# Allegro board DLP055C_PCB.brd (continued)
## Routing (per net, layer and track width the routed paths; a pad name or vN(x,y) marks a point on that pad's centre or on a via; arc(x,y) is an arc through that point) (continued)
DMD_DMUX: length 9.9
  TOP w0.191: R674.1 158.61,68.64 158.42,68.64 158.4,68.62 158.17,68.62 157.34,67.8 157.34,65.71 156.48,64.86 153.9,64.86 J502.2
DMD_DMUX0: length 32
  LY3 w0.122: J502.1 150.18,67.02 151.04,67.88 160.14,67.88 163.77,71.5 166.12,71.5 166.82,70.8 169.72,70.8 172.39,73.47 v1(177.07,73.47)
  BOTTOM w0.191: R671.2 v1(177.07,73.47)
DMD_HSSI0_CLK_N: length 22.5
  TOP w0.102: U15.AJ25 165.54,97.81 166.53,97.81 166.55,97.83 166.71,97.83 166.91,98.03 166.99,98.03
  TOP w0.127: 166.99,98.03 169.54,98.03 176.6,105.1 176.6,107.29 179.03,109.72 179.93,109.72 180.03,109.63 J7.18
DMD_HSSI0_CLK_P: length 22.5
  TOP w0.102: U15.AK25 165.65,98.4 165.53,98.28 165.53,98.1 165.62,98.01 166.45,98.01 166.47,98.03 166.63,98.03 166.69,98.09 166.69,98.16 166.87,98.34 166.99,98.34
  TOP w0.127: J7.19 180.03,110.13 179.93,110.03 178.91,110.03 176.29,107.42 176.29,105.22 169.41,98.34 166.99,98.34
DMD_HSSI0_N_0: length 25
  TOP w0.102: 166.99,101.76 166.98,101.76 166.91,101.83 166.88,101.83 166.52,101.83 166.5,101.81 165.53,101.81 U15.AJ29
  TOP w0.127: 166.99,101.76 167.27,101.76 172.76,107.25 172.76,110.72 179.76,117.72 179.93,117.72 180.03,117.63 J7.34
DMD_HSSI0_N_1: length 26
  TOP w0.102: 166.99,100.72 166.99,100.72 166.98,100.72 166.81,100.72 166.79,100.73 166.42,100.73 166.33,100.82 166.2,100.82 166.19,100.82 165.71,100.82 165.7,100.82 165.2,100.82 165.19,100.82 164.71,100.82 164.7,100.82 164.2,100.82 164.19,100.82 163.71,100.82 163.7,100.82 163.53,100.82 U15.AG28
  TOP w0.127: J7.30 179.69,115.63 173.74,109.68 173.74,107.12 167.39,100.77 167.17,100.77 167.12,100.72 166.99,100.72
DMD_HSSI0_N_2: length 23.6
  TOP w0.102: U15.AJ27 165.54,99.81 166.46,99.81 166.46,99.81 166.48,99.81 166.5,99.83 166.59,99.83 166.86,99.83 166.86,99.83 166.92,99.83 166.97,99.78 166.97,99.77 166.98,99.75 166.99,99.75
  TOP w0.127: 166.99,99.75 168.29,99.75 174.64,106.11 174.64,108.61 179.76,113.72 179.93,113.72 180.03,113.63 J7.26
DMD_HSSI0_N_3: length 24.9
  TOP w0.102: 166.99,98.74 166.87,98.74 166.83,98.77 166.78,98.77 166.67,98.77 166.67,98.77 166.42,98.77 166.4,98.79 163.56,98.79 U15.AG26
  TOP w0.127: J7.22 180.03,111.63 179.93,111.72 179.53,111.72 175.65,107.85 175.65,105.83 168.79,98.97 167.7,98.97 167.46,98.74 166.99,98.74
DMD_HSSI0_N_4: length 24
  TOP w0.102: 166.99,96.73 166.7,96.73 166.66,96.77 166.47,96.77 166.45,96.78 163.56,96.78 U15.AG24
  TOP w0.127: 166.99,96.73 167.25,96.73 167.59,97.06 170.1,97.06 177.62,104.58 177.62,106.46 178.88,107.72 179.93,107.72 180.03,107.63 J7.14
DMD_HSSI0_N_5: length 20.9
  TOP w0.102: U15.AJ23 165.54,95.81 166.53,95.81 166.56,95.83 166.68,95.83 166.92,96.07 166.99,96.07
  TOP w0.127: J7.10 180.03,105.63 179.93,105.72 179.37,105.72 178.71,105.06 178.71,104.3 170.48,96.07 166.99,96.07
DMD_HSSI0_N_6: length 22.1
  TOP w0.102: 166.99,94.69 166.87,94.69 166.82,94.73 166.46,94.73 166.41,94.78 163.57,94.78 U15.AG22
  TOP w0.127: J7.6 180.03,103.63 179.93,103.72 179.71,103.72 171.34,95.36 167.75,95.36 167.51,95.12 167.51,95.08 167.12,94.69 166.99,94.69
DMD_HSSI0_N_7: length 21.3
  TOP w0.102: U15.AJ21 165.56,93.79 166.99,93.79
  TOP w0.127: 166.99,93.79 167.33,93.79 168.17,94.63 172.44,94.63 175,97.19 177.44,97.19 178.66,98.41 178.66,101.28 179.11,101.72 179.93,101.72 180.03,101.63 J7.2
DMD_HSSI0_P_0: length 24.8
  TOP w0.102: 166.99,102.07 166.87,102.07 166.83,102.03 166.8,102.03 166.44,102.03 166.43,102.02 165.62,102.02 165.53,102.11 165.53,102.28 165.65,102.4 U15.AK29
  TOP w0.127: J7.35 180.03,118.13 179.93,118.03 179.63,118.03 172.45,110.85 172.45,107.38 167.14,102.07 166.99,102.07
DMD_HSSI0_P_1: length 26
  TOP w0.102: U15.AH28 163.65,101.4 163.51,101.26 163.51,101.12 163.61,101.02 163.78,101.02 163.79,101.02 164.11,101.02 164.11,101.02 164.78,101.02 164.79,101.02 165.11,101.02 165.11,101.02 165.78,101.02 165.79,101.02 166.11,101.02 166.11,101.02 166.41,101.02 166.5,100.93 166.89,100.93 166.99,101.03
  TOP w0.127: 166.99,101.03 167.04,101.08 167.27,101.08 173.44,107.25 173.44,109.81 179.56,115.93 179.84,115.93 180.03,116.13 J7.31
DMD_HSSI0_P_2: length 23.5
  TOP w0.102: U15.AK27 165.65,100.4 165.51,100.26 165.51,100.12 165.63,100.01 166.38,100.01 166.38,100.01 166.4,100.01 166.42,100.03 166.67,100.03 166.67,100.03 166.78,100.03 166.84,100.03 166.87,100.06 166.99,100.06
  TOP w0.127: 166.99,100.06 168.16,100.06 174.34,106.24 174.34,108.74 179.63,114.03 179.93,114.03 180.03,114.13 J7.27
DMD_HSSI0_P_3: length 24.8
  TOP w0.102: 166.99,99.04 166.98,99.04 166.97,99.03 166.97,99.02 166.92,98.97 166.86,98.97 166.86,98.97 166.59,98.97 166.5,98.97 166.48,98.99 163.64,98.99 163.51,99.12 163.51,99.26 163.65,99.4 U15.AH26
  TOP w0.127: 166.99,99.04 167.34,99.04 167.57,99.28 168.66,99.28 175.35,105.96 175.35,107.98 179.4,112.03 179.93,112.03 180.03,112.13 J7.23
DMD_HSSI0_P_4: length 23.9
  TOP w0.102: U15.AH24 163.65,97.4 163.53,97.28 163.53,97.11 163.65,96.99 166.53,96.99 166.55,96.97 166.74,96.97 166.77,96.94 166.9,96.94 166.97,97 166.97,97.02 166.98,97.04 166.99,97.04
  TOP w0.127: J7.15 180.03,108.13 179.93,108.03 178.76,108.03 177.31,106.59 177.31,104.71 169.97,97.37 167.46,97.37 167.13,97.04 166.99,97.04
DMD_HSSI0_P_5: length 20.8
  TOP w0.102: 166.99,96.38 166.95,96.38 166.6,96.03 166.47,96.03 166.46,96.01 165.62,96.01 165.53,96.11 165.53,96.28 165.65,96.4 U15.AK23
  TOP w0.127: J7.11 180.03,106.13 179.93,106.03 179.24,106.03 178.41,105.19 178.41,104.43 170.36,96.38 166.99,96.38
DMD_HSSI0_P_6: length 22
  TOP w0.102: U15.AH22 163.65,95.4 163.52,95.27 163.52,95.11 163.65,94.98 166.49,94.98 166.54,94.93 166.93,94.93 166.99,94.99
  TOP w0.127: J7.7 180.03,104.13 179.93,104.03 179.58,104.03 171.22,95.67 167.63,95.67 167.2,95.24 167.2,95.21 166.99,94.99
DMD_HSSI0_P_7: length 21.2
  TOP w0.102: 166.99,94.09 166.98,94.09 166.97,94.08 166.97,94.07 166.89,93.99 165.65,93.99 165.53,94.11 165.53,94.28 165.65,94.4 U15.AK21
  TOP w0.127: J7.3 180.03,102.13 179.93,102.03 178.98,102.03 178.35,101.41 178.35,98.53 177.31,97.49 174.88,97.49 172.31,94.93 168.05,94.93 167.2,94.09 166.99,94.09
DMD_HSSI1_CLK_N: length 32.4
  TOP w0.102: U15.AG7 163.57,79.78 166.36,79.78 166.37,79.76 166.95,79.76 166.98,79.73 166.99,79.73
  TOP w0.127: J10.18 180.03,60.1 179.93,60.19 178.42,60.19 174.57,64.04 174.57,70.58 173.57,71.58 173.57,75.24 169.08,79.73 166.99,79.73
DMD_HSSI1_CLK_P: length 32.3
  TOP w0.102: U15.AH7 163.65,80.4 163.55,80.3 163.55,80.09 163.65,79.98 166.44,79.98 166.46,79.97 166.82,79.97 166.83,79.98 166.92,79.98 166.97,80.04 166.99,80.04
  TOP w0.127: J10.19 180.03,60.6 179.93,60.5 178.54,60.5 174.88,64.17 174.88,70.71 173.88,71.71 173.88,75.36 169.2,80.04 166.99,80.04
DMD_HSSI1_N_0: length 30.8
  TOP w0.102: U15.AG11 163.57,83.78 166.93,83.78 166.98,83.73 166.99,83.73
  TOP w0.127: 166.99,83.73 171.46,83.73 173.61,81.59 174.83,81.59 177.54,78.87 177.54,76.84 177.24,76.54 177.24,74.58 177.72,74.1 177.72,68.82 178.34,68.19 179.93,68.19 180.03,68.1 J10.34
DMD_HSSI1_N_1: length 28.8
  TOP w0.102: U15.AJ10 164.98,83.36 165.01,83.36 165.55,82.83 165.69,82.83 165.71,82.82 166.19,82.82 166.2,82.83 166.45,82.83 166.45,82.83 166.81,82.83 166.81,82.83 166.93,82.83 166.98,82.78 166.99,82.78
  TOP w0.127: J10.30 180.03,66.1 179.93,66.19 178.06,66.19 176.98,67.27 176.98,72.05 176.3,72.73 176.3,77.51 171.03,82.78 166.99,82.78
DMD_HSSI1_N_2: length 31.3
  TOP w0.102: 166.99,81.73 166.98,81.73 166.95,81.76 166.37,81.76 166.35,81.78 163.57,81.78 163.05,82.3 163.05,82.3 U15.AG9
  TOP w0.127: 166.99,81.73 170.6,81.73 175.46,76.87 175.46,72.28 176.2,71.54 176.2,66.45 178.46,64.19 179.93,64.19 180.03,64.1 J10.26
DMD_HSSI1_N_3: length 30.1
  TOP w0.102: 166.99,80.75 166.97,80.75 166.92,80.8 166.84,80.8 166.81,80.83 166.45,80.83 166.43,80.8 165.54,80.8 U15.AJ8
  TOP w0.127: J10.22 180.03,62.1 179.93,62.19 178.12,62.19 175.39,64.92 175.39,71.04 174.61,71.82 174.61,75.98 169.84,80.75 166.99,80.75
DMD_HSSI1_N_4: length 30.8
  TOP w0.102: U15.AJ6 165.05,79.3 165.24,79.3 165.35,79.2 165.35,79.01 165.54,78.81 166.44,78.81 166.45,78.83 166.81,78.83 166.83,78.81 166.92,78.81 166.97,78.76 166.99,78.76
  TOP w0.127: J10.14 180.03,58.1 179.98,58.14 178.59,58.14 173.81,62.93 173.81,69.93 172.47,71.27 172.47,74.1 167.81,78.76 166.99,78.76
DMD_HSSI1_N_5: length 33
  TOP w0.102: U15.AG5 163.57,77.77 163.78,77.77 163.79,77.78 164.11,77.78 164.11,77.77 164.78,77.77 164.79,77.78 165.11,77.78 165.11,77.77 165.78,77.77 165.79,77.78 166.11,77.78 166.11,77.77 166.36,77.77 166.37,77.76 166.75,77.76 166.87,77.7
  TOP w0.127: 166.87,77.7 167,77.63 167.18,77.54 171.32,73.41 171.32,71.06 172.94,69.43 172.94,61.99 178.74,56.19 179.93,56.19 180.03,56.1 J10.10
DMD_HSSI1_N_6: length 32
  TOP w0.102: 166.99,76.56 166.93,76.56 166.71,76.78 165.56,76.78 U15.AJ4
  TOP w0.127: 166.99,76.56 166.99,76.56 168.76,74.8 168.76,72.25 170.2,70.81 170.2,70.37 172.06,68.52 172.06,61.04 175.13,57.97 175.13,57.74 178.68,54.19 179.93,54.19 180.03,54.1 J10.6
DMD_HSSI1_N_7: length 32.7
  TOP w0.102: U15.AJ2 165.56,74.78 166.92,74.78 166.97,74.73 166.99,74.73
  TOP w0.127: J10.2 180.03,52.1 179.93,52.19 179.03,52.19 171.29,59.93 171.29,68.06 168.79,70.55 167.9,70.55 167.44,71.01 167.44,72.4 167.8,72.76 167.8,73.95 167.02,74.73 166.99,74.73
DMD_HSSI1_P_0: length 30.7
  TOP w0.102: U15.AH11 163.65,84.4 163.55,84.3 163.55,84.09 163.65,83.98 166.94,83.98 166.99,84.03
  TOP w0.127: J10.35 180.03,68.6 179.93,68.5 178.47,68.5 178.02,68.94 178.02,74.22 177.54,74.71 177.54,76.41 177.85,76.72 177.85,79 174.95,81.89 173.73,81.89 171.59,84.03 166.99,84.03
DMD_HSSI1_P_1: length 28.7
  TOP w0.102: 166.99,83.08 166.98,83.08 166.93,83.03 166.37,83.03 166.37,83.03 166.12,83.03 166.11,83.02 165.79,83.02 165.77,83.03 165.63,83.03 165.53,83.14 165.53,83.28 165.65,83.4 U15.AK10
  TOP w0.127: 166.99,83.08 171.16,83.08 176.6,77.64 176.6,72.86 177.29,72.18 177.29,67.4 178.18,66.5 179.93,66.5 180.03,66.6 J10.31
DMD_HSSI1_P_2: length 31.1
  TOP w0.102: U15.AH9 163.65,82.4 163.55,82.3 163.55,82.09 163.65,81.99 166.44,81.99 166.45,81.97 166.81,81.97 166.83,81.99 166.92,81.99 166.97,82.04 166.99,82.04
  TOP w0.127: J10.27 180.03,64.6 179.93,64.5 178.58,64.5 176.51,66.58 176.51,71.66 175.76,72.4 175.76,77 170.72,82.04 166.99,82.04
DMD_HSSI1_P_3: length 29.9
  TOP w0.102: 166.99,81.06 166.98,81.06 166.96,81.03 166.37,81.03 166.34,81.01 165.63,81.01 165.55,81.09 165.55,81.3 165.65,81.4 U15.AK8
  TOP w0.127: 166.99,81.06 169.96,81.06 174.92,76.1 174.92,71.95 175.7,71.17 175.7,65.05 178.24,62.5 179.93,62.5 180.03,62.6 J10.23
DMD_HSSI1_P_4: length 30.5
  TOP w0.102: 166.99,79.07 166.98,79.07 166.95,79.03 166.37,79.03 166.35,79.02 165.63,79.02 165.55,79.09 165.55,79.3 165.65,79.4 U15.AK6
  TOP w0.127: 166.99,79.07 167.94,79.07 172.78,74.23 172.78,71.39 174.11,70.06 174.11,63.05 178.72,58.45 179.88,58.45 180.03,58.6 J10.15
DMD_HSSI1_P_5: length 32.8
  TOP w0.102: 166.99,77.97 166.45,77.97 166.45,77.98 166.2,77.98 166.19,77.98 165.71,77.98 165.7,77.98 165.2,77.98 165.19,77.98 164.71,77.98 164.7,77.98 164.2,77.98 164.19,77.98 163.71,77.98 163.7,77.98 163.66,77.98 163.55,78.09 163.55,78.3 163.65,78.4 U15.AH5
  TOP w0.127: J10.11 180.03,56.6 179.93,56.5 178.86,56.5 173.25,62.11 173.25,69.55 171.62,71.18 171.62,73.53 167.36,77.79 167.14,77.9 167.02,77.97 166.99,77.97
DMD_HSSI1_P_6: length 31.7
  TOP w0.102: 166.99,76.93 166.91,76.99 165.65,76.99 165.55,77.09 165.55,77.3 165.65,77.4 U15.AK4
  TOP w0.127: 166.99,76.93 167,76.93 167.06,76.86 167.12,76.86 169.06,74.92 169.06,72.38 170.51,70.93 170.51,70.5 172.36,68.64 172.36,61.17 175.43,58.1 175.43,57.87 178.8,54.5 179.93,54.5 180.03,54.6 J10.7
DMD_HSSI1_P_7: length 32.5
  TOP w0.102: 166.99,75.04 166.97,75.04 166.92,74.99 165.65,74.99 165.55,75.09 165.55,75.3 165.65,75.4 U15.AK2
  TOP w0.127: J10.3 180.03,52.6 179.93,52.5 179.15,52.5 171.6,60.05 171.6,68.18 168.92,70.86 168.02,70.86 167.75,71.14 167.75,72.27 168.1,72.63 168.1,74.08 167.14,75.04 166.99,75.04
DMD_LS0_CLK_N: length 47.5
  TOP w0.127: v1(179.43,121.39) 179.7,121.13 J7.41
  TOP w0.191: U15.AG17 v1(163.45,90.9)
  LY12 w0.076: 164.71,88.78 163.86,89.63 163.86,90.49 v1(163.45,90.9)
  LY12 w0.102: 164.71,88.78 166.92,88.78 166.97,88.73 166.99,88.73
  LY12 w0.114: 166.99,88.73 168.31,88.73 171.19,91.61 171.19,107.89 171.9,108.6 172.41,108.6 180.89,117.08 180.89,120.03 179.84,121.07 179.69,121.09 179.62,121.11 v1(179.43,121.39)
DMD_LS0_CLK_P: length 47.5
  TOP w0.127: J7.40 v1(179.29,120.63)
  TOP w0.191: U15.AH17 v1(164.45,90.9)
  LY12 w0.076: 164.77,88.98 164.75,88.98 164.03,89.7 164.03,90.56 164.03,90.56 164.03,90.6
  LY12 w0.102: 164.77,88.98 166.91,88.98 166.97,89.03 166.99,89.03 ; 164.03,90.6 164.01,90.62 164.01,91.3 164.12,91.4 164.35,91.4 164.49,91.26 164.49,90.94 v1(164.45,90.9)
  LY12 w0.114: 166.99,89.03 168.19,89.03 170.89,91.73 170.89,108.01 171.77,108.9 172.29,108.9 180.59,117.2 180.59,119.9 179.71,120.79 179.54,120.8 v1(179.29,120.63)
DMD_LS0_RDATA: length 53.9
  TOP w0.191: v1(178.74,123.1) 179.56,123.1 180.03,122.63 J7.44 ; U15.AH13 v1(164.45,85.9)
  LY12 w0.076: 163.03,90.36 163.03,91.24 163.2,91.41 ; 165.24,91.89 164.82,92.31 164.2,92.31 163.97,92.09
  LY12 w0.102: 163.97,92.09 163.97,91.66 163.72,91.41 163.2,91.41 ; v1(164.45,85.9) 164.96,86.41 164.96,88.1 164.53,88.53 163.56,88.53 162.93,89.16 162.93,90.25 163.03,90.36 ; 165.24,91.89 166.99,91.89
  LY12 w0.122: v1(178.74,123.1) 178.74,123.1 177.24,123.1 175.38,121.24 175.38,116.09 174.8,115.5 172.64,115.5 172.06,114.92 172.06,113.98 168.58,110.5 168.58,106.76 168.88,106.46 168.88,93 167.77,91.89 166.99,91.89
DMD_LS0_WDATA_N: length 42.6
  TOP w0.127: v1(178.74,119.77) 179.06,119.46 179.87,119.46 180.03,119.63 J7.38
  TOP w0.191: U15.AJ16 v1(165.45,89.9)
  LY12 w0.102: v1(165.45,89.9) 165.85,89.5 166.08,89.27 166.8,89.27 166.85,89.32 166.99,89.32
  LY12 w0.114: v1(178.74,119.77) 179.06,119.46 179.92,119.46 180.24,119.14 180.24,118.21 170.23,108.2 170.23,92.22 168.97,90.97 168.01,90.97 167.4,90.36 167.4,89.66 167.06,89.32 166.99,89.32
DMD_LS0_WDATA_P: length 42.6
  TOP w0.127: v1(178.74,118.9) 179.01,119.16 179.99,119.16 180,119.16 180.03,119.13 J7.37
  TOP w0.191: U15.AK16 v1(166.45,89.9)
  LY12 w0.102: 166.99,89.67 166.84,89.52 166.76,89.52 166.71,89.47 166.16,89.47 166.05,89.58 166.05,89.59 166.01,89.62 166.01,90.38 166.12,90.48 166.35,90.48 166.45,90.38 v1(166.45,89.9)
  LY12 w0.114: v1(178.74,118.9) 179.01,119.16 179.8,119.16 179.94,119.02 179.94,118.33 169.93,108.32 169.93,92.34 168.85,91.26 167.88,91.26 167.1,90.48 167.1,89.78 166.99,89.67
DMD_LS1_CLK_N: length 38
  TOP w0.191: U15.AG15 v1(163.45,87.9) ; J10.41 179.84,71.6 179.84,71.6 179.42,71.6 179.42,71.6 178.74,71.6 178.6,71.46 v1(178.56,71.46)
  BOTTOM w0.178: 166.99,81.12 166.29,81.82 164.36,81.82 163.93,82.25 163.93,83.22 162.96,84.18 162.96,87.41 v1(163.45,87.9)
  BOTTOM w0.191: v1(178.56,71.46) 179.02,71.46 179.27,71.21 180.02,71.21 180.41,70.81 180.41,68.77 179.96,68.31 176.56,68.31 167.98,76.89 167.98,80.13 166.99,81.12
DMD_LS1_CLK_P: length 30.4
  TOP w0.191: J10.40 179.84,71.1 179.84,71.1 179.42,71.1 179.42,71.1 179.08,71.1 v1(178.7,70.71) ; U15.AH15 v1(164.45,87.9)
  BOTTOM w0.178: 166.99,83.45 164.82,83.45 163.95,84.31 163.95,87.41 v1(164.45,87.9)
  BOTTOM w0.191: 166.99,83.45 167.31,83.45 168.64,82.12 168.64,76.93 174.86,70.71 v1(178.7,70.71)
DMD_LS1_RDATA: length 23.8
  TOP w0.191: v1(178.61,73.36) 178.88,73.1 J10.44 ; U15.AG13 v1(163.45,85.9)
  LY5 w0.122: v1(178.61,73.36) 169.97,82 169.97,82.48 167.05,85.4 163.94,85.4 v1(163.45,85.9)
DMD_LS1_WDATA_N: length 29.6
  TOP w0.191: v1(178.61,69.94) 178.77,70.1 179.42,70.1 179.42,70.1 179.84,70.1 179.84,70.1 J10.38 ; U15.AJ14 165.47,86.88 166.37,86.88 168.55,84.69 172,84.69 173.58,83.12 175.21,83.12 v1(178.1,80.22)
  LY12 w0.122: v1(178.1,80.22) 178.07,80.19 178.07,77.22 177.44,76.59 177.44,74.4 178.07,73.77 178.07,70.47 v1(178.61,69.94)
DMD_LS1_WDATA_P: length 30.7
  TOP w0.191: U15.AK14 166.76,87.4 167.36,86.8 168.12,86.8 169.62,85.3 172.92,85.3 173.27,84.95 173.27,84.16 173.94,83.5 175.74,83.5 v1(177.97,81.26) ; v1(178.65,69.13) 179.11,69.6 J10.37
  LY12 w0.122: v1(178.65,69.13) 177.75,70.04 177.75,73.54 177.14,74.15 177.14,77.2 177.59,77.66 177.59,80.86 177.97,81.24 v1(177.97,81.26)
DMD_OK: length 1.9
  TOP w0.191: U3.1 v1(76.07,137.16)
  BOTTOM w0.191: R87.2 75.36,137.16 v1(76.07,137.16)
DMD_P1P8V_EN: length 90.3
  TOP w0.191: R867.1 148.27,111.56 151.05,114.34 151.05,119.67 153.41,122.03 155.31,122.03 157.4,119.95 157.4,115.33 160.02,112.71 163.66,112.71 164.5,111.87 164.5,111.85 169.06,107.29 v1(171.66,107.29) ; J10.49 179.9,75.6 179.89,75.6 179.48,75.6 179.45,75.62 179.41,75.62 178.9,76.14 178.9,81.59 181.47,84.15 183.96,84.15 186.25,86.45 186.25,92.81 185.66,93.41 182.8,93.41 182.43,93.03 180.83,93.03 180.05,93.8 178.22,93.8 178,93.59 176.04,93.59 175.26,94.36 175.26,94.74 TP284.1
  LY12 w0.122: v1(171.66,107.29) 174.62,104.33 TP284.1
DMD_PWR_EN: length 95.4
  TOP w0.191: U15.R4 v1(151.45,76.9) ; J7.45 180.03,123.13 179.51,123.65 v1(179.4,123.65) ; v1(178.84,74.1) 179.32,73.62 179.43,73.62 179.46,73.59 179.88,73.59 179.91,73.62 180.97,73.62 J10.45
  LY3 w0.076: 158.89,76.19 158.77,76.31 158.28,76.31 158.27,76.31 158.24,76.31 157.91,75.98
  LY3 w0.102: 158.89,76.19 158.89,75.71 159.16,75.45 166.99,75.45 ; 155.99,73.34 157.91,75.26 157.91,75.98 ; 155.01,73.34 v1(151.45,76.9)
  LY3 w0.122: 155.01,73.34 155.08,73.27 155.92,73.27 155.99,73.34 ; 166.99,75.45 168.53,75.45 168.81,75.17 176.4,75.17 177.52,76.29 178.69,76.29 179.37,75.6 179.37,74.63 v1(178.84,74.1)
  BOTTOM w0.191: v1(178.84,74.1) 179.73,74.1 181.28,75.65 181.28,77.2 183.89,79.82 183.89,84.31 185.47,85.89 185.47,118.98 180.77,123.68 179.44,123.68 v1(179.4,123.65)
DRAIN_SEQ: length 40.3
  TOP w0.191: v1(87.29,95.89) 87.6,96.19 U525.6 ; R887.2 80.94,91.77 U526.2 84.08,91.77 84.58,92.26 84.58,92.97 84.96,93.35 88.24,93.35 88.97,94.09 88.97,94.67 88.36,95.28 87.17,95.28 86.61,95.84 86.61,97.16 v1(87.24,97.79)
  LY12 w0.122: v1(87.24,97.79) 87.78,97.25 87.78,96.38 v1(87.29,95.89) 85.67,97.5 85.67,98.84 83.79,100.72 83.79,104.02 83.18,104.63 v1(83.18,107.78)
  BOTTOM w0.191: R193.1 v1(87.24,97.79) ; U58.2 81.6,107.6 81.78,107.78 v1(83.18,107.78) 84.2,107.78 84.76,108.34 84.76,108.84 U529.4
DRV_MODE: length 2.3
  TOP w0.191: U35.14 144.21,42.52 v1(144.06,42.37)
  BOTTOM w0.191: R145.1 144.87,42.52 144.21,42.52 v1(144.06,42.37)
DRV_TRQ: length 2.5
  TOP w0.191: U35.11 144.41,44.47 144.11,44.78 v1(143.99,44.78)
  BOTTOM w0.191: v1(143.99,44.78) 144.06,44.78 144.36,45.09 R138.1
DYN_BLK: length 5.3
  TOP w0.191: J86.2 136.79,57.84 v1(138.75,57.84) 139.89,57.84 U47.2
  BOTTOM w0.191: R859.1 139.55,57.67 139.39,57.84 v1(138.75,57.84)
DYN_BLK_1: length 3.4
  TOP w0.191: R259.2 145.52,56.85 145.5,56.84 U47.4
DYN_BLK_2: length 3.5
  TOP w0.191: J114.2 147,54.36 146.99,54.37 146.99,56.35 147.02,56.39 R259.1
EEPROM_WP: length 5.3
  TOP w0.191: J72.2 32.7,77.47 U560.7
EXT_ARSTZ: length 6.5
  TOP w0.191: U15.AF29 v1(162.45,102.9)
  BOTTOM w0.191: TP21.1 162.73,107.46 162.93,107.26 162.93,103.38 162.45,102.9 v1(162.45,102.9)
EXT_I2C_EN: length 7.1
  TOP w0.191: J52.2 13.37,104.49 R586.2 17.08,104.48 U559.6
EXT_I2CPWR: length 5.8
  TOP w0.191: F1.1 7.26,102.44 J51.4
  BOTTOM w0.191: J51.4 7.02,102.76 C511.1
EXT_SCL: length 10.6
  TOP w0.191: R863.2 12.82,96.6 v1(12.82,95.97) 12.82,94.7 12.59,94.47 U17.6
  LY3 w0.122: v1(12.82,95.97) 11.86,95.97 11.4,96.43 8.3,96.43 J51.2
EXT_SCL_T: length 12
  TOP w0.191: R861.1 11,96.93 R863.1 v1(11.23,98.07) ; v1(15.74,103.77) 16.08,103.43 U559.8
  BOTTOM w0.191: v1(15.74,103.77) 15.16,103.77 14.5,103.11 14.5,100.31 13.38,99.2 12.35,99.2 v1(11.23,98.07)
EXT_SDA: length 5.8
  TOP w0.191: R864.2 10.59,93.47 U17.3 8.76,93.48 J51.1
EXT_SDA_T: length 16.8
  TOP w0.191: U559.1 16.08,98.64 15.69,98.26 v1(13.25,98.26) 12.37,99.15 10.05,99.15 9.84,98.93 R862.1 ; R864.1 v1(13.14,92.08)
  LY12 w0.122: v1(13.14,92.08) 13.14,94 12.25,94.89 12.25,97.25 v1(13.25,98.26)
FE_3D_LR: length 245.3
  TOP w0.191: v1(119.66,141.48) 119.66,141.98 119.66,141.98 119.66,142.4 119.66,142.4 119.66,142.57 119.66,142.57 119.66,142.99 119.66,142.99 J3.21 ; J42.11 135.37,9.43 135.38,9.43 135.38,9.85 135.37,9.85 v1(135.37,10.4) ; v1(118.22,9.4) 117.69,8.86 114.77,8.86 113.51,7.61 J44.51
  LY3 w0.076: 136.97,74.06 137.22,74.31 145.06,74.31 145.31,74.06 145.64,74.06
  LY3 w0.102: 150.32,73.34 150.77,73.79 v1(151.56,73.79) ; 145.64,74.06 146.25,73.45 147.7,73.45 147.81,73.34 ; 136.97,74.06 136.97,73.74 136.7,73.47 135.88,73.47
  LY3 w0.122: 135.88,73.47 135.4,73.47 135.25,73.62 126.72,73.62 126.21,74.13 123.69,74.13 122.81,75.02 v1(121.69,75.02) ; 147.81,73.34 148.17,72.98 149.97,72.98 150.32,73.34 ; v1(135.37,10.4) 135.37,11.19 134.51,12.05 125.14,12.05 124.79,12.4 121.23,12.4 v1(118.22,9.4)
  LY12 w0.122: v1(121.69,75.02) 123.06,76.39 123.06,81.25 121.11,83.2 121.11,85.98 119.55,87.54 119.55,89.39 121.11,90.94 121.11,93.76 119.45,95.42 119.45,139.49 119.66,139.7 v1(119.66,141.48) ; v1(151.56,73.79) 151.56,73.27 150.72,72.42 150.72,68.67 151.33,68.06 153.16,68.06 153.92,67.29 153.92,65.31 153.44,64.83 152.72,64.83 151.45,63.55 151.45,62.06 150.03,60.64 148.21,60.64 148.04,60.64 146.13,58.72 146.13,58.58 146.1,58.56 146.1,58.52 146.1,58.52 146.1,57.74 145.94,57.59 145.94,57.12 145.94,56.24 145,55.3 143.99,55.3 143.53,54.85 143.53,52.48 143.03,51.98 143.03,51.86 143.01,51.84 143.01,49.76 143.03,49.74 143.03,49.63 144.47,48.2 147.73,48.2 149.03,46.9 152.11,46.9 154.45,44.56 154.45,34.73 153.16,33.44 153.16,31.48 154.71,29.93 154.71,16.7 152.9,14.89 152.9,13.55 151.23,11.87 136.84,11.87 v1(135.37,10.4) ; v1(118.22,9.4) 118.22,11.85 117.22,12.86 117.22,16.21 115.02,18.41 J61.1
  BOTTOM w0.191: R260.1 151.57,74.58 151.56,74.57 v1(151.56,73.79)
FE_PROJ_ON: length 47.5
  TOP w0.191: v1(57.76,142.76) R88.1 59.06,143.08 U565.1
  LY3 w0.122: v1(57.76,142.76) 58.35,142.17 61.36,142.17 61.97,141.56 75.89,141.56 76.27,141.94 87.47,141.94 90.9,138.52 97.56,138.52 J68.1
FE_SPR1: length 3.3
  TOP w0.191: TP7.1 123.82,141.71 123.66,141.87 123.66,142.56 123.65,142.57 123.65,142.99 123.66,142.99 J3.13
FIELD: length 138.4
  TOP w0.191: J44.4 v1(89.65,8.86)
  TOP w0.381: U15.C15 v1(138.45,87.9)
  LY3 w0.076: 135.94,87.79 136.24,87.49 138.05,87.49 138.45,87.89
  LY3 w0.102: 135.94,87.79 135.88,87.79 ; v1(138.45,87.9) 138.45,87.89
  LY3 w0.122: v1(93.04,87.81) 93.04,88.78 93.16,88.9 93.16,89.04 94.81,90.69 105.46,90.69 105.83,90.33 110.24,90.33 110.62,90.72 110.63,90.72 111.74,91.83 119.02,91.83 122.17,88.68 124.61,88.68 125.22,88.07 128.22,88.07 128.22,88.08 128.23,88.08 128.25,88.1 128.64,88.1 128.67,88.08 128.84,88.08 129.13,87.79 135.88,87.79
  LY12 w0.122: v1(93.04,87.81) 92.12,86.89 92.12,63.12 98.34,56.89 98.34,51.47 89.46,42.59 89.46,19.73 89.1,19.38 89.1,12.9 90.14,11.86 90.14,9.81 89.65,9.32 v1(89.65,8.86)
FP_A_A_N: length 108.5
  TOP w0.127: J42.47 153.38,8.64 153.28,8.74 153.28,10.54 154.66,11.92 154.66,12.73 TP132.1 154.87,13.34 154.46,13.75 154.46,14.28 v1(154.74,14.57)
  TOP w0.381: U15.G2 v1(142.45,74.9)
  LY10 w0.076: v1(142.45,74.9) 142.86,74.49 144.86,74.49
  LY10 w0.102: 145.91,73.55 145.91,73.6 145.03,74.49 144.86,74.49
  LY10 w0.114: 145.91,73.55 146.1,73.37 149.16,73.37 149.24,73.28 152.85,73.28 153.64,72.49 153.64,70.69 154.22,70.12 154.22,65.25 156.23,63.24 156.23,61.64 155.68,61.09 155.68,59.73 156.99,58.42 158.38,58.42 158.86,57.93 158.86,55.52 158.41,55.06 155.79,55.06 155.1,54.37 155.1,54.04 155.69,53.45 157.54,53.45 158.07,52.93 158.07,51.84 156.13,49.9 156.13,49.26 156.58,48.81 157.46,48.81 158.24,48.03 158.24,44.31 160.95,41.6 160.95,26.25 157.75,23.05 157.75,22.26 160.04,19.97 160.04,17.21 159.63,16.8 158.54,16.8 158.21,17.13 158.21,19.2 157.94,19.47 157.54,19.47 157.27,19.2 157.27,17.14 156.85,16.72 156.06,16.72 155.65,17.14 155.65,19.07 155.36,19.36 154.75,19.36 154.46,19.07 154.46,14.86 v1(154.74,14.57)
FP_A_A_P: length 108.4
  TOP w0.127: J42.46 152.87,8.64 152.97,8.74 152.97,10.67 154.35,12.05 154.35,12.34 TP135.1 154.03,13.34 154.15,13.46 154.15,14.28 v1(153.87,14.57)
  TOP w0.381: U15.G1 v1(142.45,73.9)
  LY10 w0.076: 144.86,74.29 144.85,74.29 144.84,74.3 144.79,74.3 144.77,74.31 142.86,74.31 v1(142.45,73.9)
  LY10 w0.102: 145.7,73.34 145.69,73.35 145.69,73.46 144.86,74.29
  LY10 w0.114: v1(153.87,14.57) 154.16,14.87 154.16,19.2 154.63,19.66 155.48,19.66 155.95,19.2 155.95,17.26 156.19,17.02 156.73,17.02 156.97,17.26 156.97,19.32 157.41,19.76 158.07,19.76 158.51,19.32 158.51,17.25 158.67,17.1 159.5,17.1 159.74,17.34 159.74,19.85 157.45,22.14 157.45,23.17 160.66,26.38 160.66,41.47 157.94,44.19 157.94,47.91 157.34,48.51 156.46,48.51 155.83,49.14 155.83,50.02 157.77,51.96 157.77,52.8 157.42,53.15 155.56,53.15 154.8,53.92 154.8,54.49 155.67,55.36 158.28,55.36 158.56,55.64 158.56,57.81 158.25,58.12 156.87,58.12 155.38,59.61 155.38,61.21 155.93,61.76 155.93,63.12 153.92,65.13 153.92,69.99 153.34,70.57 153.34,72.36 152.72,72.98 149.12,72.98 149.03,73.07 145.97,73.07 145.7,73.34
FP_A_B_N: length 108.6
  TOP w0.127: J42.44 151.87,8.64 151.78,8.74 151.78,10.85 152.55,11.62 152.55,14.44 TP138.1 152.68,15.24 152.55,15.37 152.55,15.93 v1(152.84,16.22)
  TOP w0.381: U15.F4 v1(141.45,76.9)
  LY10 w0.076: 142.1,73.34 142.1,73.36 142.03,73.42 142.03,76.16 141.7,76.49 141.52,76.49 141.45,76.56 v1(141.45,76.9)
  LY10 w0.114: 142.1,73.34 142.1,73.12 142.24,72.98 143.24,72.98 144.55,71.67 146.59,71.67 147.16,71.1 147.16,60.49 147.68,59.97 149.24,59.97 149.76,60.49 149.76,63.61 150.78,64.63 153.19,64.63 154.5,63.31 154.5,59.34 155.29,58.54 155.29,56.24 153.84,54.78 153.84,52.53 154.53,51.84 154.53,48.83 157.08,46.28 157.08,43.62 159.76,40.93 159.76,28.52 158.88,27.63 150.3,27.63 149.76,27.09 149.76,24.58 150.3,24.04 154.29,24.04 155.16,23.16 155.16,21.4 152.73,18.96 152.73,16.69 152.84,16.58 v1(152.84,16.22)
FP_A_B_P: length 108.5
  TOP w0.127: J42.43 151.38,8.64 151.47,8.74 151.47,10.97 152.25,11.75 152.25,14.44 TP141.1 152.12,15.24 152.25,15.37 152.25,15.93 v1(151.96,16.22)
  TOP w0.381: U15.F3 v1(141.45,75.9)
  LY10 w0.076: 141.8,73.34 141.8,73.36 141.86,73.42 141.86,76.09 141.63,76.31 141.52,76.31 141.45,76.24 v1(141.45,75.9)
  LY10 w0.114: 141.8,73.34 141.8,72.99 142.11,72.68 143.12,72.68 144.43,71.37 146.46,71.37 146.86,70.98 146.86,60.37 147.55,59.67 149.36,59.67 150.06,60.37 150.06,63.48 150.9,64.33 153.06,64.33 154.2,63.19 154.2,59.21 155,58.42 155,56.36 153.54,54.9 153.54,52.41 154.23,51.71 154.23,48.7 156.78,46.16 156.78,43.5 159.47,40.81 159.47,28.64 158.75,27.93 150.18,27.93 149.47,27.22 149.47,24.46 150.18,23.75 154.16,23.75 154.87,23.04 154.87,21.52 152.43,19.09 152.43,16.69 v1(151.96,16.22)
FP_A_C_N: length 108.5
  TOP w0.127: v1(150.93,14.44) 150.65,14.16 150.65,13.78 150.65,13.46 150.77,13.34 TP131.1 150.65,12.53 150.65,11.19 150.28,10.82 150.28,8.74 150.38,8.64 J42.41
  TOP w0.381: U15.E2 v1(140.45,74.9)
  LY10 w0.076: v1(140.45,74.9) 140.45,74.56 140.52,74.49 140.7,74.49 141.03,74.16 141.03,73.42 141.1,73.36 141.1,73.34
  LY10 w0.114: 141.1,73.34 141.1,73.13 141.45,72.78 141.45,71.81 143.33,69.93 143.33,62.8 146.35,59.78 146.35,58.71 152.04,53.02 152.04,46.95 155.8,43.19 155.8,29.9 154.56,28.67 148.08,28.67 147.61,29.13 147.61,30.05 148.02,30.45 148.92,30.45 149.51,29.86 152.05,29.86 152.22,30.03 152.22,32.38 151.67,32.94 147.27,32.94 146.74,32.4 146.74,24.41 144.16,21.83 144.16,21.07 144.57,20.66 149.85,20.66 150.82,19.7 150.82,15 150.93,14.88 v1(150.93,14.44)
FP_A_C_P: length 108.3
  TOP w0.127: J42.40 149.87,8.64 149.97,8.74 149.97,10.95 150.34,11.32 150.34,12.53 TP134.1 150.22,13.34 150.34,13.46 150.34,13.65 150.34,14.16 v1(150.06,14.44)
  TOP w0.381: U15.E1 v1(140.45,73.9)
  LY10 w0.076: 140.8,73.34 140.8,73.36 140.86,73.42 140.86,74.08 140.63,74.31 140.52,74.31 140.45,74.24 v1(140.45,73.9)
  LY10 w0.114: 140.8,73.34 140.8,73.01 141.15,72.66 141.15,71.68 143.03,69.81 143.03,62.67 146.05,59.65 146.05,58.58 151.74,52.89 151.74,46.82 155.5,43.07 155.5,30.03 154.44,28.96 148.2,28.96 147.91,29.26 147.91,29.92 148.14,30.15 148.8,30.15 149.39,29.56 152.17,29.56 152.52,29.91 152.52,32.51 151.79,33.24 147.15,33.24 146.44,32.53 146.44,24.53 143.86,21.96 143.86,20.95 144.45,20.36 149.72,20.36 150.52,19.57 150.52,14.91 v1(150.06,14.44)
FP_A_CLK_N: length 108.5
  TOP w0.127: v1(145.22,16.35) 144.93,16.06 144.93,15.68 144.93,15.37 145.06,15.24 TP136.1 144.88,14.39 144.88,11.95 145.78,11.05 145.78,8.74 145.87,8.64 J42.32
  TOP w0.381: U15.H4 v1(143.45,76.9)
  LY10 w0.076: 152.33,76.06 151.4,76.06 150.97,76.49 143.86,76.49 v1(143.45,76.9)
  LY10 w0.102: 154.97,73.55 152.47,76.05 152.33,76.06
  LY10 w0.114: 154.97,73.55 155.09,73.43 155.09,72.66 157.42,70.33 157.42,61.44 159.81,59.05 159.81,53.55 159.26,52.99 159.26,45.08 161.97,42.36 161.97,25.67 160.02,23.72 160.02,22.28 161.03,21.27 161.03,15.17 159.03,13.17 145.99,13.17 145.13,14.03 145.13,15.47 145.94,16.29 145.94,16.75 145.69,17 145.36,17 145.23,16.87 145.23,16.63 145.22,16.63 v1(145.22,16.35)
FP_A_CLK_P: length 108.4
  TOP w0.127: J42.31 145.37,8.64 145.47,8.74 145.47,10.92 144.57,11.82 144.57,14.49 TP139.1 144.5,15.24 144.63,15.37 144.63,15.55 144.63,16.06 v1(144.34,16.35)
  TOP w0.381: U15.H3 v1(143.45,75.9)
  LY10 w0.076: 152.47,75.63 152.22,75.88 151.33,75.88 150.9,76.31 143.86,76.31 v1(143.45,75.9)
  LY10 w0.102: 152.47,75.63 154.76,73.34
  LY10 w0.114: 154.76,73.34 154.79,73.31 154.79,72.54 157.12,70.21 157.12,61.32 159.51,58.92 159.51,53.67 158.96,53.11 158.96,44.95 161.67,42.24 161.67,25.8 159.72,23.84 159.72,22.15 160.73,21.14 160.73,15.29 158.9,13.46 146.11,13.46 145.42,14.15 145.42,15.35 146.24,16.17 146.24,16.88 145.82,17.3 145.24,17.3 144.93,16.99 144.93,16.76 144.81,16.64 144.63,16.64 v1(144.34,16.35)
FP_A_D_N: length 108.4
  TOP w0.127: J42.38 148.87,8.64 148.78,8.74 148.78,14.47 TP137.1 148.93,15.24 148.8,15.37 148.8,15.99 v1(149.03,16.22)
  TOP w0.381: U15.D4 v1(139.45,76.9)
  LY10 w0.076: v1(139.45,76.9) 139.45,76.56 139.52,76.49 139.7,76.49 140.03,76.16 140.03,73.42 140.1,73.36 140.1,73.34
  LY10 w0.114: v1(149.03,16.22) 148.74,16.5 148.74,18.85 147.91,19.69 143.28,19.69 142.76,20.21 142.76,22.03 145.79,25.06 145.79,33.19 146.4,33.8 153.72,33.8 154.61,34.68 154.61,41.46 154.23,41.84 153.22,41.84 152.76,41.38 152.76,35.9 152.53,35.67 151.86,35.67 151.68,35.85 151.68,44.39 151.3,44.77 151.3,45.57 149.55,47.33 149.55,49.08 150.31,49.85 150.31,51.54 147.61,54.23 147.61,55.86 145.31,58.17 143.36,58.17 142.2,59.32 142.2,63.56 141.68,64.08 141.68,67.3 140.67,68.31 139.54,68.31 139.38,68.47 139.38,71.37 140.1,72.08 140.1,73.34
FP_A_D_P: length 108.2
  TOP w0.127: J42.37 148.38,8.64 148.47,8.74 148.47,14.4 TP140.1 148.31,15.24 148.5,15.43 148.5,15.87 v1(148.15,16.22)
  TOP w0.381: U15.D3 v1(139.45,75.9)
  LY10 w0.076: 139.8,73.34 139.8,73.36 139.86,73.42 139.86,76.08 139.63,76.31 139.52,76.31 139.45,76.24 v1(139.45,75.9)
  LY10 w0.114: 139.8,73.34 139.8,72.2 139.08,71.49 139.08,68.35 139.42,68.01 140.55,68.01 141.38,67.18 141.38,63.96 141.91,63.43 141.91,59.2 143.24,57.87 145.18,57.87 147.32,55.74 147.32,54.11 150.01,51.42 150.01,49.97 149.25,49.21 149.25,47.2 151,45.45 151,44.65 151.38,44.27 151.38,35.73 151.74,35.37 152.65,35.37 153.06,35.78 153.06,41.26 153.34,41.54 154.1,41.54 154.31,41.34 154.31,34.8 153.6,34.1 146.27,34.1 145.5,33.32 145.5,25.19 142.46,22.16 142.46,20.08 143.16,19.39 147.79,19.39 148.44,18.73 148.44,16.51 v1(148.15,16.22)
FP_A_E_N: length 108.2
  TOP w0.127: J42.35 147.37,8.64 147.28,8.74 147.28,12.22 146.98,12.51 146.98,12.68 TP130.1 147.09,13.34 146.86,13.57 146.86,14.18 v1(147.12,14.44)
  TOP w0.381: U15.C2 v1(138.45,74.9)
  LY10 w0.076: 138.97,73.34 139.03,73.41 139.03,74.16 138.7,74.49 138.52,74.49 138.45,74.56 v1(138.45,74.9)
  LY10 w0.114: 138.97,73.34 138.93,73.3 138.93,73.21 138.7,72.99 138.7,70.72 137.73,69.75 137.73,68.5 140.33,65.9 140.33,64.32 139.77,63.76 135.11,63.76 134.81,63.46 134.81,60.15 135.1,59.87 137.49,59.87 137.87,60.25 137.87,62.14 138.47,62.74 140.54,62.74 141.17,62.11 141.17,58.25 143.79,55.63 143.79,54.44 144.88,53.35 144.88,49.73 150.75,43.87 150.75,40.22 150.29,39.76 148.14,39.76 147.65,39.26 147.65,37.65 147.16,37.17 141.98,37.17 141.63,36.81 141.63,34.52 142.02,34.12 144.14,34.12 144.7,33.56 144.7,25.6 141.55,22.44 141.55,19.43 142.53,18.46 146.67,18.46 147.4,17.73 147.4,15.83 146.83,15.25 146.83,14.74 v1(147.12,14.44)
FP_A_E_P: length 108.2
  TOP w0.127: v1(146.25,14.44) 146.55,14.14 146.55,13.48 146.41,13.34 TP133.1 146.97,12.09 146.97,8.74 146.87,8.64 J42.34
  TOP w0.381: U15.C1 v1(138.45,73.9)
  LY10 w0.076: 138.7,73.41 138.71,73.42 138.73,73.42 138.74,73.44 138.74,73.49 138.86,73.6 138.86,74.08 138.63,74.31 138.52,74.31 138.45,74.24 v1(138.45,73.9)
  LY10 w0.114: v1(146.25,14.44) 146.53,14.73 146.53,15.38 147.1,15.95 147.1,17.6 146.55,18.16 142.4,18.16 141.25,19.31 141.25,22.57 144.4,25.72 144.4,33.44 144.02,33.82 141.9,33.82 141.33,34.39 141.33,36.94 141.86,37.47 147.04,37.47 147.35,37.78 147.35,39.39 148.02,40.06 150.16,40.06 150.45,40.34 150.45,43.74 144.58,49.61 144.58,53.23 143.49,54.32 143.49,55.51 140.87,58.13 140.87,61.99 140.42,62.44 138.6,62.44 138.17,62.02 138.17,60.13 137.62,59.57 134.97,59.57 134.51,60.03 134.51,63.59 134.99,64.06 139.65,64.06 140.03,64.45 140.03,65.78 137.44,68.38 137.44,69.87 138.4,70.84 138.4,73.11 138.7,73.41
FP_B_A_N: length 108.3
  TOP w0.127: v1(141.41,16.22) 141.12,15.93 141.12,15.55 141.12,15.37 141.25,15.24 TP86.1 141.12,14.44 141.12,11.71 142.78,10.06 142.78,8.74 142.88,8.64 J42.26
  TOP w0.305: U15.D5 v1(139.45,77.9)
  LY10 w0.076: 136.05,77.13 136.24,77.31 138.7,77.31 139.03,77.64 139.03,77.82 139.11,77.9 v1(139.45,77.9)
  LY10 w0.114: v1(141.41,16.22) 141.12,16.51 141.12,16.95 139.33,18.74 139.33,23.09 142.26,26.03 142.26,27.85 137.56,32.55 137.56,35.64 141.88,39.96 141.88,41.18 143.13,42.43 143.13,43.92 141.34,45.7 141.34,47.41 142.69,48.76 142.69,52.03 140.26,54.46 135.16,54.46 133.1,56.52 133.1,58.34 132.28,59.17 128.06,59.17 127.22,60.01 127.22,65.92 128.34,67.04 131.01,67.04 131.71,67.74 131.71,70.51 130.69,71.53 129.12,71.53 128.67,71.99 128.67,73.56 130.08,74.98 131.31,74.98 132.06,74.23 135.37,74.23 135.93,74.79 135.93,77 136.05,77.13
FP_B_A_P: length 108.4
  TOP w0.127: v1(140.53,16.22) 140.82,15.93 140.82,15.42 140.82,15.37 140.69,15.24 TP89.1 140.82,14.44 140.82,11.59 142.47,9.93 142.47,8.74 142.38,8.64 J42.25
  TOP w0.381: U15.C5 v1(138.45,77.9)
  LY10 w0.076: 135.88,77.35 136.01,77.49 138.63,77.49 138.86,77.72 138.86,77.82 138.79,77.9 v1(138.45,77.9)
  LY10 w0.114: 135.88,77.35 135.86,77.35 135.63,77.13 135.63,74.91 135.25,74.53 132.18,74.53 131.43,75.28 129.96,75.28 128.37,73.69 128.37,71.87 129,71.23 130.57,71.23 131.41,70.39 131.41,67.87 130.89,67.34 128.22,67.34 126.92,66.04 126.92,59.88 127.94,58.87 132.15,58.87 132.8,58.22 132.8,56.39 135.04,54.16 140.14,54.16 142.39,51.9 142.39,48.88 141.04,47.53 141.04,45.58 142.83,43.79 142.83,42.55 141.58,41.31 141.58,40.09 137.26,35.76 137.26,32.43 141.96,27.72 141.96,26.15 139.03,23.22 139.03,18.62 140.82,16.83 140.82,16.5 v1(140.53,16.22)
FP_B_B_N: length 108.3
  TOP w0.127: v1(139.5,14.67) 139.22,14.39 139.22,13.46 139.34,13.34 TP79.1 139.22,12.53 139.22,11.92 141.28,9.86 141.28,8.74 141.37,8.64 J42.23
  TOP w0.381: U15.B6 v1(137.45,78.9)
  LY10 w0.076: v1(137.45,78.9) 137.11,78.9 137.03,78.82 137.03,78.64 136.7,78.31 135.96,78.31 135.9,78.25 135.88,78.25
  LY10 w0.114: 135.88,78.25 135.71,78.25 135.5,78.04 135.5,77.53 133.79,75.81 131.27,75.81 130.72,76.37 130.72,77.59 130.39,77.91 129.02,77.91 128.71,77.6 128.71,74.93 127.46,73.68 127.46,67.86 125.41,65.81 125.41,58.89 125.95,58.35 130.62,58.35 131.32,57.65 131.32,54.79 132.53,53.58 139.54,53.58 141.55,51.57 141.55,49.1 140.15,47.7 140.15,43.37 139.5,42.71 136.04,42.71 135.61,42.28 135.61,32.91 141.09,27.42 141.09,26.25 138.22,23.38 138.22,17.76 139.22,16.76 139.22,14.96 v1(139.5,14.67)
FP_B_B_P: length 108.5
  TOP w0.127: v1(138.63,14.67) 138.91,14.39 138.91,13.46 138.79,13.34 TP82.1 138.91,12.53 138.91,11.8 140.97,9.74 140.97,8.74 140.88,8.64 J42.22
  TOP w0.381: U15.A6 v1(136.45,78.9)
  LY10 w0.076: v1(136.45,78.9) 136.78,78.9 136.86,78.82 136.86,78.72 136.63,78.49 135.96,78.49 135.9,78.55 135.88,78.55
  LY10 w0.114: v1(138.63,14.67) 138.92,14.97 138.92,16.64 137.92,17.63 137.92,23.5 140.79,26.37 140.79,27.3 135.31,32.79 135.31,42.41 135.91,43.01 139.38,43.01 139.85,43.49 139.85,47.83 141.25,49.22 141.25,51.45 139.42,53.28 132.41,53.28 131.02,54.66 131.02,57.53 130.5,58.05 125.83,58.05 125.11,58.77 125.11,65.93 127.16,67.98 127.16,73.81 128.41,75.05 128.41,77.73 128.89,78.21 130.52,78.21 131.01,77.71 131.01,76.49 131.39,76.11 133.67,76.11 135.2,77.65 135.2,78.16 135.59,78.55 135.88,78.55
FP_B_C_N: length 108.4
  TOP w0.127: J42.20 139.88,8.64 139.78,8.74 139.78,9.74 137.31,12.2 137.31,14.44 TP85.1 137.44,15.24 137.31,15.37 137.31,16.09 v1(137.6,16.37)
  TOP w0.381: U15.D7 v1(139.45,79.9)
  LY10 w0.076: v1(139.45,79.9) 139.11,79.9 139.03,79.82 139.03,79.64 138.7,79.31 135.96,79.31 135.9,79.25 135.88,79.25
  LY10 w0.114: 135.88,79.25 135.32,79.25 135.15,79.42 134.4,79.42 133.9,78.93 128.53,78.93 126.21,76.6 126.21,74.26 125.12,73.17 124.02,73.17 123.1,72.25 123.1,68.47 124.38,67.19 124.38,58.27 126.21,56.44 126.21,53.02 126.7,52.53 137.3,52.53 138.43,51.39 138.43,47.31 137.51,46.39 134.48,46.39 133.75,45.66 133.75,42.73 134.6,41.88 134.6,32.32 139.45,27.47 139.45,26 137.31,23.86 137.31,16.67 v1(137.6,16.37)
FP_B_C_P: length 108.6
  TOP w0.127: v1(136.72,16.37) 137.01,16.09 137.01,15.37 136.88,15.24 TP88.1 137.01,14.44 137.01,12.08 139.47,9.61 139.47,8.74 139.37,8.64 J42.19
  TOP w0.381: U15.C7 v1(138.45,79.9)
  LY10 w0.076: 135.88,79.55 135.9,79.55 135.96,79.49 138.63,79.49 138.86,79.72 138.86,79.82 138.79,79.9 v1(138.45,79.9)
  LY10 w0.114: 135.88,79.55 135.44,79.55 135.27,79.72 134.27,79.72 133.78,79.22 128.41,79.22 125.91,76.73 125.91,74.38 125,73.47 123.9,73.47 122.81,72.37 122.81,68.34 124.09,67.06 124.09,58.14 125.91,56.31 125.91,52.89 126.58,52.23 137.18,52.23 138.14,51.27 138.14,47.44 137.39,46.69 134.36,46.69 133.46,45.78 133.46,42.61 134.3,41.76 134.3,32.2 139.15,27.35 139.15,26.13 137.01,23.98 137.01,16.66 v1(136.72,16.37)
FP_B_CLK_N: length 108.4
  TOP w0.127: J42.29 144.38,8.64 144.28,8.74 144.28,10.49 143.03,11.74 143.03,12.53 TP80.1 143.15,13.34 143.03,13.46 143.03,14.21 v1(143.31,14.5)
  TOP w0.381: U15.B4 v1(137.45,76.9)
  LY10 w0.076: 137.1,73.34 137.1,73.36 137.03,73.42 137.03,76.82 137.11,76.9 v1(137.45,76.9)
  LY10 w0.114: 137.1,73.34 137.1,72.61 136.64,72.15 135.58,72.15 134.51,73.23 131.84,73.23 131.59,72.97 131.59,72.01 132.08,71.52 135.86,71.52 136.57,70.8 136.57,68.55 133.31,65.29 129.07,65.29 128.55,64.76 128.55,64.1 129.23,63.42 129.23,61.26 130.27,60.21 132.77,60.21 134.13,58.85 134.13,57.79 134.63,57.3 137.06,57.3 138.95,55.41 141.02,55.41 143.79,52.64 143.79,48.55 145.89,46.44 145.89,40.55 144.95,39.6 144.95,38.59 144.37,38.01 141.21,38.01 139.75,36.55 139.75,32.29 143.33,28.7 143.33,25.67 140.43,22.77 140.43,18.88 143.03,16.28 143.03,14.78 v1(143.31,14.5)
FP_B_CLK_P: length 108.4
  TOP w0.127: J42.28 143.87,8.64 143.97,8.74 143.97,10.36 142.72,11.61 142.72,12.53 TP83.1 142.6,13.34 142.72,13.46 142.72,14.21 v1(142.44,14.5)
  TOP w0.381: U15.A4 v1(136.45,76.9)
  LY10 w0.076: v1(136.45,76.9) 136.78,76.9 136.86,76.82 136.86,73.42 136.8,73.36 136.8,73.34
  LY10 w0.114: 136.8,73.34 136.8,72.73 136.52,72.45 135.7,72.45 134.63,73.52 131.72,73.52 131.29,73.1 131.29,71.89 131.96,71.22 135.73,71.22 136.27,70.68 136.27,68.67 133.19,65.59 128.95,65.59 128.25,64.89 128.25,63.98 128.93,63.3 128.93,61.13 130.14,59.91 132.65,59.91 133.84,58.73 133.84,57.67 134.5,57 136.93,57 138.83,55.11 140.89,55.11 143.49,52.51 143.49,48.42 145.6,46.32 145.6,40.67 144.65,39.72 144.65,38.71 144.25,38.31 141.08,38.31 139.45,36.67 139.45,32.16 143.03,28.58 143.03,25.8 140.13,22.9 140.13,18.75 142.73,16.15 142.73,14.79 v1(142.44,14.5)
FP_B_D_N: length 108.4
  TOP w0.127: v1(135.3,14.98) 135.01,14.69 135.01,13.7 135.14,13.57 TP78.1 135.26,13.03 135.26,12.64 138.28,9.63 138.28,8.74 138.38,8.64 J42.17
  TOP w0.381: U15.B8 v1(137.45,80.9)
  LY10 w0.076: v1(137.45,80.9) 137.11,80.9 137.03,80.82 137.03,80.64 136.7,80.31 136.05,80.31 135.89,80.15 135.88,80.15
  LY10 w0.114: v1(135.3,14.98) 135,15.27 134.82,15.27 134.72,15.38 134.72,22.03 133.84,22.91 123.03,22.91 117.01,28.93 117.01,41.76 118.62,43.37 118.62,45.37 117.25,46.74 116.98,46.74 115.62,48.09 115.62,56.53 119.5,60.41 119.5,67.67 120.33,68.49 120.33,72.24 123.41,75.32 123.41,76.99 125.39,78.97 126.49,78.97 128.68,81.16 133.74,81.16 134.77,80.13 135.81,80.13 135.83,80.15 135.88,80.15
FP_B_D_P: length 108.4
  TOP w0.127: v1(134.42,14.98) 134.71,14.69 134.71,13.7 134.58,13.57 TP81.1 137.97,9.5 137.97,8.74 137.88,8.64 J42.16
  TOP w0.381: U15.A8 v1(136.45,80.9)
  LY10 w0.076: v1(136.45,80.9) 136.79,80.9 136.86,80.82 136.86,80.72 136.63,80.49 135.88,80.49
  LY10 w0.114: 135.88,80.49 135.85,80.49 135.8,80.43 134.89,80.43 133.86,81.46 128.56,81.46 126.37,79.27 125.27,79.27 123.11,77.11 123.11,75.45 120.03,72.36 120.03,68.61 119.2,67.79 119.2,60.53 115.32,56.65 115.32,47.97 116.85,46.44 117.13,46.44 118.32,45.25 118.32,43.49 116.71,41.88 116.71,28.81 122.9,22.61 133.71,22.61 134.42,21.91 v1(134.42,14.98)
FP_B_E_N: length 109.2
  TOP w0.127: J42.14 136.88,8.64 136.78,8.74 136.78,10.14 135.61,11.31 133.79,11.31 131.69,13.42 131.69,13.9 TP84.1 132.11,14.84 131.83,15.12 131.83,15.96 v1(132.12,16.25)
  TOP w0.305: U15.D9 v1(139.45,81.9)
  LY10 w0.076: v1(139.45,81.9) 139.11,81.9 139.03,81.82 139.03,81.62 138.73,81.31 135.88,81.31
  LY10 w0.114: v1(132.12,16.25) 131.82,16.56 131.82,17 126.95,21.86 122.72,21.86 116.02,28.56 116.02,45.47 114.41,47.09 114.41,57.71 115.08,58.38 115.08,64.42 116.4,65.74 116.4,67.01 118.45,69.05 118.45,73.48 128.53,83.57 134.14,83.57 134.33,83.37 134.33,82.86 135.88,81.31
FP_B_E_P: length 109.2
  TOP w0.127: J42.13 136.37,8.64 136.47,8.74 136.47,10.01 135.48,11.01 133.67,11.01 131.38,13.29 131.38,14.19 TP87.1 131.05,14.84 131.53,15.32 131.53,15.96 v1(131.24,16.25)
  TOP w0.381: U15.C9 v1(138.45,81.9)
  LY10 w0.076: v1(138.45,81.9) 138.79,81.9 138.86,81.82 138.86,81.69 138.66,81.49 136.09,81.49 135.97,81.6 135.97,81.64 135.96,81.65
  LY10 w0.114: v1(131.24,16.25) 131.52,16.52 131.52,16.87 126.83,21.57 122.59,21.57 115.72,28.43 115.72,45.35 114.11,46.96 114.11,57.83 114.79,58.5 114.79,64.55 116.11,65.87 116.11,67.14 118.15,69.18 118.15,73.61 128.41,83.87 134.26,83.87 134.63,83.5 134.63,82.98 135.96,81.65
FPDLINK_IIC0_EN: length 10.1
  BOTTOM w0.191: U36.6 120.08,6.86 120.08,6.86 120.08,7.27 120.08,7.28 120.08,8.13 120.57,8.62 121.85,8.62 R590.2 122.76,13.45 J64.1
FPDLINK_IIC1_EN: length 11.5
  TOP w0.191: J64.3 126.13,12.79 126.13,11.13 v1(125.27,10.27) 125.25,10.3 v1(123.62,10.3)
  BOTTOM w0.191: v1(123.62,10.3) 123.62,8.52 123.26,8.16 123.26,7.32 123.26,7.32 123.26,6.9 123.26,6.9 U37.6 ; R581.2 v1(125.27,10.27)
GPIO_18: length 43.2
  TOP w0.191: U15.R5 v1(150.45,77.9)
  LY3 w0.122: v1(150.45,77.9) 150.45,77.9 149.95,78.41 134.34,78.41 133.9,78.85 131.19,78.85 128.7,81.34 121.43,81.34 120.72,80.63 111.42,80.63 J87.2
GPIO_18_TST_PD: length 35.7
  LY3 w0.122: J87.3 J76.3
  LY12 w0.122: J89.3 J87.3
  BOTTOM w0.191: J78.3 110.08,95.98 110.08,93.25 111.68,91.65 111.68,90.59 112.93,89.34 R157.1 112.93,87.46 113.53,86.85 119.02,86.85 119.53,86.34 119.53,83.91 119.06,83.44 J76.3
GPIO_18_TST_PU: length 30.5
  TOP w0.191: J89.1 J87.1 R156.1 116.6,75.6 117.83,75.6 J76.1
  LY12 w0.122: J78.1 108.9,87.5 110.66,85.73 110.66,84.26 111.38,83.55 111.38,78.04 J87.1
GPIO_19: length 60.7
  TOP w0.191: U15.P1 149.95,73.49 149.94,73.48 149.94,73.34 149.75,73.15 148.49,73.15 148.04,72.7 148.04,71.59 147.98,71.53 147.98,71.35 148.06,71.27 148.06,68.43 147.98,68.35 147.98,68.34 146.93,67.29 145.72,67.29 v1(145.08,66.66)
  LY3 w0.122: v1(145.08,66.66) 144.73,67.01 138.61,67.01 137.65,67.98 136.22,67.98 135.73,67.5 127.04,67.5 126.73,67.19 120.08,67.19 119.16,68.11 112.33,68.11 111.52,68.92 111.52,69.66 110.96,70.22 108.6,70.22 107.31,71.51 107.31,75.29 107.62,75.6 107.62,78.12 J89.2
GPIO_20: length 36
  TOP w0.191: U15.P2 v1(149.45,74.9)
  LY3 w0.076: 149.98,77.03 149.71,77.31 149.62,77.31 149.62,77.31 149.28,77.31 149.27,77.31 147.62,77.31 147.62,77.31 147.28,77.31 147.27,77.31 146.62,77.31 146.62,77.31 146.28,77.31 146.27,77.31 145.62,77.31 145.62,77.31 145.28,77.31 145.27,77.31 144.62,77.31 144.62,77.31 144.28,77.31 144.27,77.31 143.62,77.31 143.62,77.31 143.28,77.31 143.27,77.31 142.62,77.31 142.62,77.31 142.28,77.31 142.27,77.31 141.62,77.31 141.62,77.31 141.28,77.31 141.27,77.31 140.62,77.31 140.62,77.31 140.28,77.31 140.27,77.31 139.62,77.31 139.62,77.31 139.28,77.31 139.27,77.31 138.62,77.31 138.62,77.31 138.28,77.31 138.27,77.31 137.62,77.31 137.62,77.31 137.28,77.31 137.27,77.31 136.62,77.31 136.62,77.31 136.28,77.31 136.19,77.22 135.88,77.22
  LY3 w0.102: 149.98,77.03 149.98,75.42 149.46,74.9 v1(149.45,74.9)
  LY3 w0.122: 135.88,77.22 135.6,77.22 135.39,77.02 134.69,77.02 134.16,76.49 134.16,76.49 133.89,76.22 133.78,76.11 130.8,76.11 128.82,78.09 120.35,78.09 J76.2
GPIO_21: length 57.4
  TOP w0.191: U15.P3 v1(149.45,75.9)
  LY3 w0.076: 136.09,76.55 136.16,76.49 136.28,76.49 136.28,76.49 136.62,76.49 136.62,76.49 137.28,76.49 137.28,76.49 137.62,76.49 137.62,76.49 138.28,76.49 138.28,76.49 138.62,76.49 138.62,76.49 139.28,76.49 139.28,76.49 139.62,76.49 139.62,76.49 140.28,76.49 140.28,76.49 140.62,76.49 140.62,76.49 141.28,76.49 141.28,76.49 141.62,76.49 141.62,76.49 142.28,76.49 142.28,76.49 142.62,76.49 142.62,76.49 143.28,76.49 143.28,76.49 143.62,76.49 143.62,76.49 144.28,76.49 144.28,76.49 144.62,76.49 144.62,76.49 145.28,76.49 145.28,76.49 145.62,76.49 145.62,76.49 146.28,76.49 146.28,76.49 146.62,76.49 146.62,76.49 147.27,76.49 147.28,76.49 147.62,76.49 147.62,76.49 148.84,76.49
  LY3 w0.102: v1(149.45,75.9) 149.43,75.9 148.84,76.49 ; 136.09,76.55 135.97,76.55
  LY3 w0.122: v1(114.03,77.51) 114.6,77.51 115.23,78.14 119.92,78.14 120.56,77.5 121.56,77.5 121.7,77.64 128.88,77.64 130.69,75.84 133.86,75.84 133.87,75.85 133.88,75.85 133.99,75.96 134,75.96 134.42,76.38 134.42,76.38 134.71,76.67 135.86,76.67 135.97,76.55
  LY12 w0.122: v1(114.03,77.51) 113.99,77.55 113.99,81.82 111.1,84.72 111.1,88.45 110.44,89.11 110.44,93.08 J78.2
GPIO_32: length 5
  TOP w0.191: U15.Y4 v1(156.45,76.9)
  BOTTOM w0.191: R124.2 155.95,73.33 155.95,76.41 v1(156.45,76.9)
GPIO_33: length 1.8
  TOP w0.191: U15.Y2 v1(156.45,74.9)
  BOTTOM w0.191: R127.2 156.45,73.94 v1(156.45,74.9)
GPIO_34: length 2.5
  TOP w0.191: R675.2 155.95,73.11 155.95,73.11 U15.Y1
GPIO_35: length 8.8
  TOP w0.191: R676.2 141.48,109.52 141.48,109.15 141.02,108.7 141.02,105.11 142.52,103.62 142.52,102.8 142.92,102.4 U15.G29
GPIO_36: length 20
  TOP w0.191: v1(149.02,113.55) 147.6,113.55 147.14,113.09 144.27,113.09 143.15,111.97 143.15,109.2 142.9,108.95 141.76,108.95 141.38,108.57 141.38,107.58 141.37,107.57 141.37,106.83 141.38,106.82 141.38,106.54 141.37,106.53 141.37,105.79 141.38,105.78 141.38,105.36 142.95,103.79 U15.G30
  BOTTOM w0.191: v1(149.02,113.55) R613.2 R677.2
GPIO_37: length 29.7
  TOP w0.102: U15.H26 v1(143.45,99.9)
  BOTTOM w0.191: v1(143.45,99.9) 143.34,99.9 142.85,100.39 142.17,100.39 141.96,100.61 141.96,102.37 142.26,102.68 142.26,104.2 141.32,105.14 141.32,108.4 142.23,109.31 144.67,109.31 145.59,110.22 148.64,110.22 149.63,111.21 152.7,111.21 153.41,111.92 153.41,112.89 152.75,113.55 R601.2 R678.2
GPIO_38: length 12.4
  TOP w0.191: R614.2 140.02,109.33 140.02,108.42 v1(140.48,107.96) 140.48,107.67 R168.2 ; U15.H27 v1(143.45,100.9)
  LY3 w0.122: v1(140.48,107.96) 140.48,106.92 142.94,104.46 142.94,101.4 v1(143.45,100.9)
GPIO_39: length 12.3
  TOP w0.191: U15.H28 v1(143.45,101.9)
  LY12 w0.122: v1(143.45,101.9) 143.45,103.52 140.61,106.36 v1(137.38,106.36)
  BOTTOM w0.191: R615.2 R169.2 137.58,106.16 v1(137.38,106.36)
GPIO_40: length 4.6
  TOP w0.191: U15.H29 143.45,102.9 143.45,103.85 141.92,105.38 R18.2
GPIO_41: length 3.1
  TOP w0.191: R19.2 143.93,105.42 143.93,103.88 143.95,103.86 U15.H30
GPIO_42: length 8.6
  TOP w0.191: U15.J26 v1(144.45,99.9)
  BOTTOM w0.191: R104.2 144.45,106.16 143.8,105.51 143.8,104.94 142.96,104.1 142.96,100.7 143.25,100.42 143.93,100.42 v1(144.45,99.9)
GPIO_43: length 8.8
  TOP w0.191: U15.J27 v1(144.45,100.9)
  BOTTOM w0.191: R870.2 146.99,106.16 146.48,105.65 146.48,104.89 146.05,104.46 144.07,104.46 143.77,104.16 143.77,102.43 143.93,102.28 143.93,101.42 v1(144.45,100.9)
GPIO_44: length 5.5
  TOP w0.191: R871.2 145.05,106.51 145.05,104.93 144.45,104.33 144.45,102.9 U15.J29
GPIO_45: length 16
  TOP w0.191: U15.J30 144.95,104.14 145.36,104.56 147.6,104.56 147.82,104.78 147.82,105.72 148.48,106.38 149.42,106.38 149.7,106.66 149.7,107.91 149.42,108.19 149.42,109.74 149.19,109.97 R867.2 R866.2 R679.2
GPIO_46: length 23.5
  TOP w0.191: v1(150.19,109.38) 150.22,109.38 R868.2 ; U15.K27 v1(145.45,100.9)
  BOTTOM w0.191: v1(145.45,100.9) 145.93,101.38 146.71,101.38 146.96,101.63 146.96,104.53 149.78,107.35 149.78,108.97 v1(150.19,109.38) 152.09,109.38 152.32,109.15 153.49,109.15 R680.2 159.18,109.97 J82.2
GPIO_59: length 7.2
  TOP w0.191: U15.AG1 164.1,73.25 165.33,73.25 166.05,72.53 J505.2
GPIO_59B: length 3.9
  BOTTOM w0.191: R711.2 R710.2 J505.3
HBT_CLKOUT: length 202.9
  TOP w0.185: J500.8 v1(50.37,9.78)
  LY3 w0.122: v1(55.57,105.9) 56.79,107.12 61.4,107.12 66.73,112.45 83.38,112.45 84.32,111.51 88.24,111.51 98.55,101.2 107.06,101.2 108.58,99.68 111.2,99.68 111.86,100.34 128.26,100.34 v1(129.18,101.26)
  LY12 w0.122: v1(55.57,105.9) 55.57,102.45 56.94,101.08 56.94,85.96 49.88,78.9 49.88,67.6 42.21,59.93 42.21,41.66 46.55,37.32 46.55,15.68 47.75,14.49 47.75,12.48 50.37,9.85 v1(50.37,9.78)
  BOTTOM w0.191: R169.1 136.09,107.2 135.05,106.16 135.05,105.04 133.3,103.29 130.86,103.29 130.32,102.75 130.32,102.4 v1(129.18,101.26)
HBT_DO: length 207.3
  TOP w0.185: J500.6 v1(49.37,9.65)
  TOP w0.191: R168.1 138.07,106.16 137.46,105.55 136.32,105.55 135.86,105.09 135.86,102.96 v1(134.9,101.99)
  LY3 w0.122: v1(57.2,110.24) 57.22,110.24 61.34,114.36 75.38,114.36 76.55,113.2 91.71,113.2 97.15,107.76 106.02,107.76 106.45,107.32 111.35,107.32 115.06,103.62 128.9,103.62 130.53,101.99 v1(134.9,101.99)
  LY12 w0.122: v1(49.37,9.65) 49.37,10.27 47.42,12.23 47.42,13.98 46.15,15.25 46.15,35.09 41.47,39.76 41.47,47.89 40.33,49.03 40.33,50.91 41.22,51.8 41.22,60 48.87,67.65 48.87,78.44 56.24,85.82 56.24,100.63 54.68,102.19 54.68,107.73 v1(57.2,110.24)
